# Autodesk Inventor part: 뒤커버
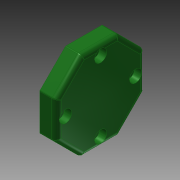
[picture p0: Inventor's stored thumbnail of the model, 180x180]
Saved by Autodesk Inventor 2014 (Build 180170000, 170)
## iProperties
Created: 2015-11
Part Number: 뒤커버
Material: 알루미늄 6061
Document SubType Name: Modeling
Designer: mduedu
Density: 1 g/cm^3
Appearance: 매끄러움 - 짙은 산림 녹색
Author: mduedu
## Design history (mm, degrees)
sketch "스케치5" dims "d66" = 58
  geometry: L1 (12.012, 29)-(29, 12.012); L2 (29, 12.012)-(29, -12.012); L3 (29, -12.012)-(12.012, -29); L4 (12.012, -29)-(-12.012, -29); L5 (-12.012, -29)-(-29, -12.012); L6 (-29, -12.012)-(-29, 12.012); L7 (-29, 12.012)-(-12.012, 29); L8 (-12.012, 29)-(12.012, 29); 4 further points
  constraints: 16 end point, 2 coincident, 2 vertical alignment, 1 midpoint, 19 other
extrude "돌출2" new body sketch "스케치5" distance "d67" = 11; taper "d68" = 0 deg
sketch "스케치6"
  geometry: C1 r 16 at (0, 0); 1 further point
  constraints: 1 centre point, 1 coincident
  dimensions: "d69" = 32 diameter of C1
extrude "돌출3" join sketch "스케치6" distance "d70" = 3; taper "d71" = 0 deg
hole "구멍5" diameter "d74" = 28; stored, may be unused: countersink angle "d78" = 90 deg, drill point angle "d80" = 0 deg; dims "d75" = 6, "d76" = 4, "d77" = 2, "d79" = 10, "d98" = 10, "d99" = 10
fillet "모깎기7" dims "d81" = 1
fillet "모깎기8" dims "d82" = 3
fillet "모깎기9" dims "d83" = 3
fillet "모깎기10" dims "d84" = 0.3
sketch "스케치7" dims "d85" = 46
  geometry: 3 further points
  constraints: 2 vertical alignment, 1 coincident, 2 other
hole "구멍6" sketch "스케치7" at (0, 23) diameter "d86" = 4.5; stored, may be unused: countersink angle "d90" = 90 deg, drill point angle "d92" = 0 deg; dims "d87" = 6, "d88" = 8, "d89" = 4.6, "d91" = 10
node "솔리드2"
pattern_circular "원형 패턴3" dims angle "d94" = 360 deg
